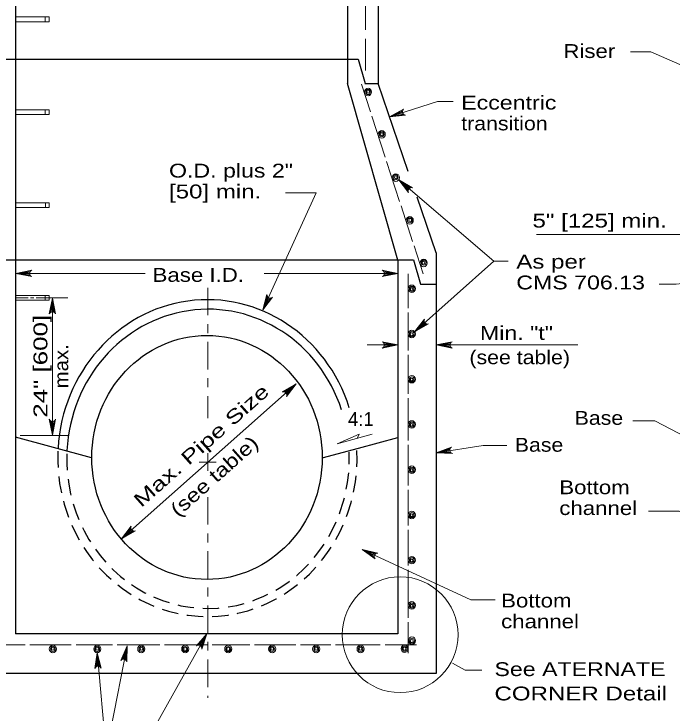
# Model space of a CAD drawing. Extents: x 808.4 to 842.4, y 1034.6 to 1056.6.
# Drawn here: x 812.55 to 819.97, y 1039.13 to 1047.01 of the extents above; entities that cross this region are included whole.
import ezdxf
from ezdxf.enums import TextEntityAlignment as Align

# ---------------------------------------------------------------- set-up
doc = ezdxf.new("R2010")
doc.units = 0
doc.header["$LTSCALE"] = 0.062
for name, pattern in [('DOT_DASHED', [7.7, 5, -1.2, 0.3, -1.2]), ('LONG_DASHED', [7.5, 6, -1.5]), ('MEDIUM_DASHED', [4.5, 3, -1.5])]:
    doc.linetypes.add(name, pattern=pattern)
doc.layers.add('1', color=7, linetype='Continuous', lineweight=13)
doc.layers.add('10', color=7, linetype='Continuous')

msp = doc.modelspace()

# ---------------------------------------------------------------- linework, layer by layer
at = {"layer": '1', "lineweight": 25}
for p, q in [((812.56975, 1051.63983), (812.56975, 1040.02425)), ((816.30875, 1051.64075), (816.30875, 1046.22608)), ((816.65425, 1051.31108), (816.65425, 1046.22608)), ((812.45517, 1046.49917), (816.43017, 1046.49917)), ((816.87875, 1044.23425), (816.30875, 1046.22608)), ((816.50708, 1046.22592), (816.64317, 1046.22592)), ((816.99533, 1045.2345), (816.65425, 1046.22608)), ((817.311, 1044.31725), (817.09592, 1044.94225)), ((817.311, 1044.31725), (817.311, 1039.57592)), ((816.87875, 1044.23425), (816.87875, 1040.02533)), ((813.42633, 1042.00583), (812.57, 1042.23808)), ((816.43342, 1042.11633), (816.8765, 1042.23658)), ((816.02592, 1042.00583), (816.43342, 1042.11633)), ((816.87675, 1040.02425), (812.56975, 1040.02425)), ((817.311, 1039.57592), (812.15217, 1039.57592))]:
    msp.add_line(p, q, dxfattribs=at)
at = {"layer": '1', "linetype": 'LONG_DASHED'}
msp.add_line((816.5125, 1051.44942), (816.5125, 1046.37117), dxfattribs=at)
at = {"layer": '1'}
for p, q in [((812.57058, 1046.97442), (812.94867, 1046.97442)), ((812.90425, 1046.92175), (812.90425, 1046.97467)), ((812.94867, 1046.92142), (812.94867, 1046.97442)), ((812.57058, 1046.92142), (812.94867, 1046.92142)), ((816.46692, 1046.21758), (816.56825, 1045.90583)), ((812.57058, 1045.92833), (812.94867, 1045.92833)), ((812.9045, 1045.87592), (812.9045, 1045.92892)), ((812.94867, 1045.87525), (812.94867, 1045.92833)), ((816.93058, 1045.91708), (816.78433, 1045.84808)), ((812.57058, 1045.87525), (812.94867, 1045.87525)), ((816.58425, 1045.85667), (816.73483, 1045.39358)), ((816.92875, 1045.90492), (816.78433, 1045.84808)), ((816.9305, 1045.89358), (816.78433, 1045.84808)), ((816.9375, 1045.88067), (816.78433, 1045.84808)), ((816.9465, 1045.87258), (816.78433, 1045.84808)), ((816.75075, 1045.3445), (816.89742, 1044.89375)), ((817.00308, 1045.03925), (816.88675, 1045.13892)), ((816.99583, 1045.0265), (816.88675, 1045.13892)), ((816.99375, 1045.01458), (816.88675, 1045.13892)), ((817.01167, 1045.04675), (816.88675, 1045.13892)), ((817.023, 1045.05167), (816.88675, 1045.13892)), ((815.35608, 1043.6735), (815.95767, 1044.9935)), ((815.95767, 1044.9935), (815.60967, 1044.9935)), ((812.57058, 1044.88208), (812.94867, 1044.88208)), ((812.57058, 1044.82908), (812.94867, 1044.82908)), ((812.90525, 1044.82917), (812.90525, 1044.88217)), ((812.94867, 1044.82908), (812.94867, 1044.88208)), ((816.91342, 1044.84458), (817.044, 1044.44308)), ((820.47083, 1044.52517), (818.43792, 1044.52517)), ((817.06, 1044.39392), (817.16242, 1044.079)), ((817.95933, 1044.22242), (817.06642, 1043.42775)), ((812.73483, 1044.10675), (812.57458, 1044.08433)), ((816.7185, 1044.10675), (816.87875, 1044.08433)), ((812.72942, 1044.09567), (812.57458, 1044.08433)), ((812.72775, 1044.08433), (812.57458, 1044.08433)), ((812.73058, 1044.07), (812.57458, 1044.08433)), ((812.73675, 1044.05958), (812.57458, 1044.08433)), ((812.57458, 1044.08433), (814.03008, 1044.08433)), ((815.36975, 1044.08433), (816.87875, 1044.08433)), ((816.71667, 1044.05958), (816.87875, 1044.08433)), ((816.72275, 1044.07), (816.87875, 1044.08433)), ((816.72392, 1044.09567), (816.87875, 1044.08433)), ((816.72558, 1044.08433), (816.87875, 1044.08433)), ((816.99517, 1044.07833), (816.99517, 1043.69333)), ((817.13133, 1043.96275), (817.3105, 1043.96275)), ((812.56967, 1043.80892), (812.71192, 1043.80892)), ((812.57058, 1043.83592), (812.94867, 1043.83592)), ((812.7385, 1043.80892), (812.77542, 1043.80892)), ((812.80208, 1043.80892), (813.16025, 1043.80892)), ((812.90492, 1043.78292), (812.90492, 1043.83592)), ((812.94867, 1043.78292), (812.94867, 1043.83592)), ((812.96058, 1043.64258), (812.98533, 1043.80467)), ((812.97092, 1043.64867), (812.98533, 1043.80467)), ((812.98533, 1043.80467), (812.98533, 1042.26375)), ((812.98533, 1043.6515), (812.98533, 1043.80467)), ((812.99667, 1043.64992), (812.98533, 1043.80467)), ((813.00775, 1043.64442), (812.98533, 1043.80467)), ((815.40658, 1043.82725), (815.35608, 1043.6735)), ((815.41417, 1043.8175), (815.35608, 1043.6735)), ((815.42358, 1043.811), (815.35608, 1043.6735)), ((815.44975, 1043.80817), (815.35608, 1043.6735)), ((815.43775, 1043.80725), (815.35608, 1043.6735)), ((812.57058, 1043.78292), (812.94867, 1043.78292)), ((816.99517, 1043.64417), (816.99517, 1043.218)), ((817.173, 1043.54942), (817.06642, 1043.42775)), ((817.17617, 1043.5375), (817.06642, 1043.42775)), ((817.18233, 1043.52783), (817.06642, 1043.42775)), ((817.19392, 1043.51875), (817.06642, 1043.42775)), ((817.20533, 1043.51492), (817.06642, 1043.42775)), ((816.87875, 1043.27883), (816.53133, 1043.27883)), ((816.71667, 1043.25408), (816.87875, 1043.27883)), ((816.7185, 1043.30125), (816.87875, 1043.27883)), ((816.72275, 1043.26442), (816.87875, 1043.27883)), ((816.72392, 1043.29017), (816.87875, 1043.27883)), ((816.72558, 1043.27883), (816.87875, 1043.27883)), ((817.47125, 1043.30125), (817.311, 1043.27883)), ((817.46575, 1043.29017), (817.311, 1043.27883)), ((817.46417, 1043.27883), (817.311, 1043.27883)), ((817.467, 1043.26442), (817.311, 1043.27883)), ((817.47308, 1043.25408), (817.311, 1043.27883)), ((817.311, 1043.27883), (818.90558, 1043.27883)), ((816.99517, 1043.16892), (816.99517, 1042.72642)), ((813.76358, 1041.09308), (815.73042, 1042.84042)), ((815.59275, 1042.75125), (815.73042, 1042.84042)), ((815.60425, 1042.74758), (815.73042, 1042.84042)), ((815.61592, 1042.73867), (815.73042, 1042.84042)), ((815.62217, 1042.72917), (815.73042, 1042.84042)), ((815.6255, 1042.71725), (815.73042, 1042.84042)), ((816.99517, 1042.67725), (816.99517, 1042.20192)), ((812.96292, 1042.424), (812.98533, 1042.26375)), ((812.974, 1042.41858), (812.98533, 1042.26375)), ((813.01008, 1042.42592), (812.98533, 1042.26375)), ((812.99975, 1042.41975), (812.98533, 1042.26375)), ((812.98533, 1042.41692), (812.98533, 1042.26375)), ((812.62258, 1042.25667), (813.16567, 1042.25667)), ((816.19475, 1042.1655), (816.58983, 1042.27275)), ((816.99517, 1042.15283), (816.99517, 1041.69392)), ((814.73583, 1042.05883), (814.73583, 1041.85933)), ((817.46583, 1042.11133), (817.311, 1042.0645)), ((817.46217, 1042.0995), (817.311, 1042.0645)), ((817.46233, 1042.08808), (817.311, 1042.0645)), ((817.46733, 1042.07425), (817.311, 1042.0645)), ((817.475, 1042.065), (817.311, 1042.0645)), ((814.63992, 1041.9585), (814.83008, 1041.9585)), ((816.99517, 1041.64475), (816.99517, 1041.24317)), ((813.8685, 1041.21625), (813.76358, 1041.09308)), ((813.87175, 1041.20442), (813.76358, 1041.09308)), ((813.87808, 1041.19483), (813.76358, 1041.09308)), ((813.88975, 1041.18592), (813.76358, 1041.09308)), ((816.99517, 1041.194), (816.99517, 1040.79242)), ((813.90125, 1041.18225), (813.76358, 1041.09308)), ((816.614, 1040.91142), (816.47492, 1040.97558)), ((816.6105, 1040.89717), (816.47492, 1040.97558)), ((816.61175, 1040.88517), (816.47492, 1040.97558)), ((816.62025, 1040.921), (816.47492, 1040.97558)), ((816.62983, 1040.92883), (816.47492, 1040.97558)), ((816.99517, 1040.74333), (816.99517, 1040.20242)), ((816.99517, 1040.15333), (816.99517, 1039.80617)), ((814.63925, 1039.89475), (814.72483, 1040.02425)), ((814.64992, 1039.89067), (814.72483, 1040.02425)), ((814.66117, 1039.88117), (814.72483, 1040.02425)), ((814.66717, 1039.87075), (814.72483, 1040.02425)), ((812.67817, 1039.89975), (812.36392, 1039.89975)), ((813.19667, 1039.89975), (812.73225, 1039.89975)), ((813.66108, 1039.89975), (813.25083, 1039.89975)), ((813.82633, 1039.8885), (813.592, 1038.69192)), ((814.19517, 1039.89975), (813.71517, 1039.89975)), ((813.77092, 1039.7365), (813.82633, 1039.8885)), ((813.78283, 1039.7395), (813.82633, 1039.8885)), ((813.79433, 1039.73875), (813.82633, 1039.8885)), ((813.80775, 1039.733), (813.82633, 1039.8885)), ((813.81667, 1039.72483), (813.82633, 1039.8885)), ((814.72917, 1039.89975), (814.24925, 1039.89975)), ((815.20908, 1039.89975), (814.78333, 1039.89975)), ((815.72775, 1039.89975), (815.26317, 1039.89975)), ((816.1225, 1039.89975), (815.78183, 1039.89975)), ((816.67975, 1039.89975), (816.17658, 1039.89975)), ((817.0875, 1039.89975), (816.73383, 1039.89975)), ((813.47608, 1039.65), (813.4905, 1039.81117)), ((813.48683, 1039.656), (813.4905, 1039.81117)), ((813.49808, 1039.65817), (813.4905, 1039.81117)), ((813.51258, 1039.65608), (813.4905, 1039.81117)), ((813.52333, 1039.65042), (813.4905, 1039.81117))]:
    msp.add_line(p, q, dxfattribs=at)
at = {"layer": '1', "linetype": 'DOT_DASHED'}
for p, q in [((814.73583, 1043.92275), (814.73583, 1042.45483)), ((814.73583, 1041.56392), (814.73583, 1039.30083))]:
    msp.add_line(p, q, dxfattribs=at)
at = {"layer": '1'}
for points in [[(820.44242, 1046.26842), (819.72975, 1046.58067), (819.50075, 1046.58067)], [(816.78433, 1045.84808), (817.32592, 1046.02242), (817.50142, 1046.02242)], [(816.96383, 1045.86692), (816.78433, 1045.84808), (816.94275, 1045.9345)], [(816.99808, 1044.99683), (816.88675, 1045.13892), (817.04417, 1045.05058)], [(816.88675, 1045.13892), (817.95933, 1044.22242), (818.11958, 1044.22242)], [(812.75158, 1044.049), (812.57458, 1044.08433), (812.75158, 1044.11975)], [(816.70175, 1044.049), (816.87875, 1044.08433), (816.70175, 1044.11975)], [(820.60308, 1044.0305), (820.01208, 1043.96475), (819.82133, 1043.96475)], [(812.94992, 1043.62767), (812.98533, 1043.80467), (813.02075, 1043.62767)], [(815.46583, 1043.81683), (815.35608, 1043.6735), (815.40233, 1043.848)], [(817.2235, 1043.51658), (817.06642, 1043.42775), (817.17725, 1043.57017)], [(816.70175, 1043.24342), (816.87875, 1043.27883), (816.70175, 1043.31425)], [(817.488, 1043.24342), (817.311, 1043.27883), (817.488, 1043.31425)], [(815.57458, 1042.74933), (815.73042, 1042.84042), (815.62158, 1042.69642)], [(813.02075, 1042.44075), (812.98533, 1042.26375), (812.94992, 1042.44075)], [(820.47083, 1042.05842), (819.77183, 1042.42392), (819.52642, 1042.42392)], [(816.19475, 1042.1655), (816.44142, 1042.27267), (816.42083, 1042.22633)], [(817.311, 1042.0645), (817.838, 1042.14692), (818.10508, 1042.14692)], [(817.49133, 1042.05675), (817.311, 1042.0645), (817.48042, 1042.12675)], [(821.00275, 1040.98675), (820.04792, 1041.40742), (819.70025, 1041.40742)], [(813.91942, 1041.18417), (813.76358, 1041.09308), (813.87242, 1041.23708)], [(816.62083, 1040.86933), (816.47492, 1040.97558), (816.65042, 1040.93358)], [(816.47492, 1040.97558), (817.70058, 1040.40775), (817.97533, 1040.40775)], [(814.62692, 1039.89542), (814.72483, 1040.02425), (814.13883, 1038.97683), (814.73583, 1038.97683)], [(814.66917, 1039.85258), (814.72483, 1040.02425), (814.60742, 1039.88717)], [(813.82392, 1039.70808), (813.82633, 1039.8885), (813.75467, 1039.72283)], [(813.48992, 1039.82542), (813.592, 1038.69192), (813.12325, 1038.69192)], [(813.53467, 1039.63608), (813.4905, 1039.81117), (813.46392, 1039.63258)], [(817.492, 1039.69117), (817.63425, 1039.61325), (817.825, 1039.61325)]]:
    msp.add_lwpolyline(points, dxfattribs=at)
at = {"layer": '1', "lineweight": 25}
for points in [[(816.43017, 1046.49917), (816.50775, 1046.22592), (816.65367, 1046.22592)], [(812.41425, 1044.23608), (817.05442, 1044.23608), (817.13217, 1043.96275), (817.31108, 1043.96275)]]:
    msp.add_lwpolyline(points, dxfattribs=at)
at = {"layer": '1'}
msp.add_circle((816.90332, 1040.01355), 0.65247, dxfattribs=at)
for centre, start, end in [((816.96693, 1045.90497), 129.38833, 265.21446), ((817.03203, 1045.01445), 71.48719, 207.31331), ((812.7659, 1044.0844), 112.08782, 247.91395), ((816.68748, 1044.0844), 292.08605, 67.91218), ((815.44033, 1043.84527), 175.95078, 311.77691), ((812.98536, 1043.6134), 22.08782, 157.91395), ((817.21117, 1043.55275), 152.89039, 288.71652), ((816.68748, 1043.27887), 292.08605, 67.91218), ((817.50226, 1043.27887), 112.08782, 247.91395), ((815.58741, 1042.71334), 333.70574, 109.53187), ((812.98528, 1042.45505), 202.08782, 337.91395), ((817.49997, 1042.09399), 120.95578, 256.78191), ((813.90656, 1041.22017), 153.70574, 289.53187), ((816.64862, 1040.89549), 87.32536, 223.15148), ((814.63128, 1039.85743), 352.82059, 128.64672), ((813.78628, 1039.70149), 10.00721, 145.83334), ((813.49995, 1039.62009), 24.92489, 160.75102)]:
    msp.add_arc(centre, 0.0382, start, end, dxfattribs=at)
for centre, major_axis in [((816.54161, 1046.12894), (0, 0.04232)), ((816.54216, 1046.12911), (0, -0.02865)), ((816.54153, 1046.13119), (0, -0.01649)), ((816.69626, 1045.65113), (0, 0.04232)), ((816.69603, 1045.6528), (0, -0.02865)), ((816.69768, 1045.65288), (0, -0.01649)), ((816.85486, 1045.16441), (0, 0.04232)), ((816.85313, 1045.16766), (0, -0.02865)), ((816.85423, 1045.16808), (0, -0.01649)), ((817.0114, 1044.68211), (0, 0.04232)), ((817.01195, 1044.68435), (0, -0.02865)), ((817.01526, 1044.6866), (0, -0.01649)), ((817.16811, 1044.20213), (0, 0.04232)), ((817.16913, 1044.2063), (0, -0.02865)), ((817.16693, 1044.20505), (0, -0.01649)), ((817.03445, 1043.91197), (0, 0.04232)), ((817.03516, 1043.9103), (0, -0.02865)), ((817.03319, 1043.90789), (0, -0.01649)), ((817.03445, 1043.40226), (0, 0.04232)), ((817.03516, 1043.40059), (0, -0.02865)), ((817.03319, 1043.39818), (0, -0.01649)), ((817.03445, 1042.89255), (0, 0.04232)), ((817.03516, 1042.89089), (0, -0.02865)), ((817.03319, 1042.88847), (0, -0.01649)), ((817.03445, 1042.38285), (0, 0.04232)), ((817.03516, 1042.38118), (0, -0.02865)), ((817.03319, 1042.37877), (0, -0.01649)), ((817.03445, 1041.87314), (0, 0.04232)), ((817.03516, 1041.87148), (0, -0.02865)), ((817.03319, 1041.86906), (0, -0.01649)), ((817.03445, 1041.36343), (0, 0.04232)), ((817.03516, 1041.36177), (0, -0.02865)), ((817.03319, 1041.35935), (0, -0.01649)), ((817.03445, 1040.85373), (0, 0.04232)), ((817.03516, 1040.85206), (0, -0.02865)), ((817.03319, 1040.84965), (0, -0.01649)), ((817.03445, 1040.34402), (0, 0.04232)), ((817.03516, 1040.34236), (0, -0.02865)), ((817.03319, 1040.33994), (0, -0.01649)), ((817.03634, 1039.94675), (0, 0.04232)), ((817.03705, 1039.94509), (0, -0.02865)), ((817.03508, 1039.94267), (0, -0.01649)), ((812.9902, 1039.85347), (0, 0.04232)), ((812.99036, 1039.85405), (0, -0.02865)), ((812.99044, 1039.8543), (0, -0.01649)), ((813.49052, 1039.85347), (0, 0.04232)), ((813.48989, 1039.85405), (0, -0.02865)), ((813.48997, 1039.8543), (0, -0.01649)), ((813.98612, 1039.85347), (0, 0.04232)), ((813.98793, 1039.85405), (0, -0.02865)), ((813.98801, 1039.8543), (0, -0.01649)), ((814.48172, 1039.85347), (0, 0.04232)), ((814.48085, 1039.85231), (0, -0.02865)), ((814.48093, 1039.85256), (0, -0.01649)), ((814.96599, 1039.85347), (0, 0.04232)), ((814.96686, 1039.85231), (0, -0.02865)), ((814.96678, 1039.85256), (0, -0.01649)), ((815.46159, 1039.85347), (0, 0.04232)), ((815.45978, 1039.85405), (0, -0.02865)), ((815.4597, 1039.8543), (0, -0.01649)), ((815.95719, 1039.85347), (0, 0.04232)), ((815.95782, 1039.85405), (0, -0.02865)), ((815.95774, 1039.8543), (0, -0.01649)), ((816.45751, 1039.85347), (0, 0.04232)), ((816.45735, 1039.85405), (0, -0.02865)), ((816.45728, 1039.8543), (0, -0.01649)), ((816.95358, 1039.85497), (0, 0.04232)), ((816.95358, 1039.8558), (0, -0.02865)), ((816.9535, 1039.85605), (0, -0.01649))]:
    msp.add_ellipse(centre, major_axis=major_axis, ratio=0.944544, dxfattribs=at)
at = {"layer": '1', "lineweight": 25}
for centre, major_axis, start_param, end_param in [((814.73147, 1042.00339), (0, 1.7855), 5.0364615, 7.7917895), ((814.73826, 1041.99523), (0, 1.68595), 5.0458682, 7.797991)]:
    msp.add_ellipse(centre, major_axis=major_axis, ratio=0.944544, start_param=start_param, end_param=end_param, dxfattribs=at)
msp.add_ellipse((814.72699, 1042.01079), major_axis=(0, 1.37483), ratio=0.944544, dxfattribs=at)
at = {"layer": '1', "linetype": 'MEDIUM_DASHED', "lineweight": 25}
for centre, major_axis, start_param, end_param in [((814.73147, 1042.00339), (0, 1.7855), 1.526051, 4.7671396), ((814.73826, 1041.99523), (0, 1.68595), 1.5366438, 4.7571755)]:
    msp.add_ellipse(centre, major_axis=major_axis, ratio=0.944544, start_param=start_param, end_param=end_param, dxfattribs=at)

# ---------------------------------------------------------------- texts
at = {"layer": '1'}
for s, width, p in [('See ATERNATE', 1.25, (817.96617, 1039.54733)), ('CORNER Detail', 1.3, (817.96617, 1039.27333))]:
    msp.add_text(s, height=0.156, dxfattribs=dict(at, width=width)).set_placement(p)
at = {"layer": '10'}
for s, width, p in [('Riser', 1.2, (818.74283, 1046.51233)), ('Eccentric', 1.25, (817.59142, 1045.93167)), ('transition', 1.15, (817.59142, 1045.697)), ('O.D. plus 2"', 1.25, (814.29875, 1045.16483)), ('[50] min.', 1.3, (814.29875, 1044.93017)), ('5" [125] min.', 1.3, (818.39442, 1044.60183)), ('As per', 1.3, (818.21217, 1044.13942)), ('Base I.D.', 1.2, (814.11392, 1043.98992)), ('CMS 706.13', 1.25, (818.21217, 1043.90475)), ('Base', 1.15, (818.8695, 1042.37875)), ('Base', 1.15, (818.195, 1042.07567)), ('Bottom', 1.2, (818.69667, 1041.59708)), ('channel', 1.2, (818.69667, 1041.36242)), ('Bottom', 1.2, (818.04108, 1040.3205)), ('channel', 1.2, (818.04108, 1040.08583))]:
    msp.add_text(s, height=0.156, dxfattribs=dict(at, width=width)).set_placement(p)
for s, width, p in [('24" [600]', 1.4, (812.92808, 1043.03837)), ('max.', 1.1, (813.16275, 1043.03833))]:
    msp.add_text(s, height=0.156, rotation=90, dxfattribs=dict(at, width=width)).set_placement(p, align=Align.CENTER)
for s, width, p in [('Min. "t" ', 1.25, (818.25063, 1043.33608)), ('(see table)', 1.15, (818.25058, 1043.06208))]:
    msp.add_text(s, height=0.156, dxfattribs=dict(at, width=width)).set_placement(p, align=Align.CENTER)
for s, width, p in [('Max. Pipe Size', 1.4, (813.98567, 1041.43992)), ('(see table)', 1.25, (814.4005, 1041.33325))]:
    msp.add_text(s, height=0.156, rotation=41.617, dxfattribs=dict(at, width=width)).set_placement(p)
msp.add_text('4:1', height=0.156, dxfattribs=at).set_placement((816.31558, 1042.36558))

doc.saveas('drawing.dxf')
